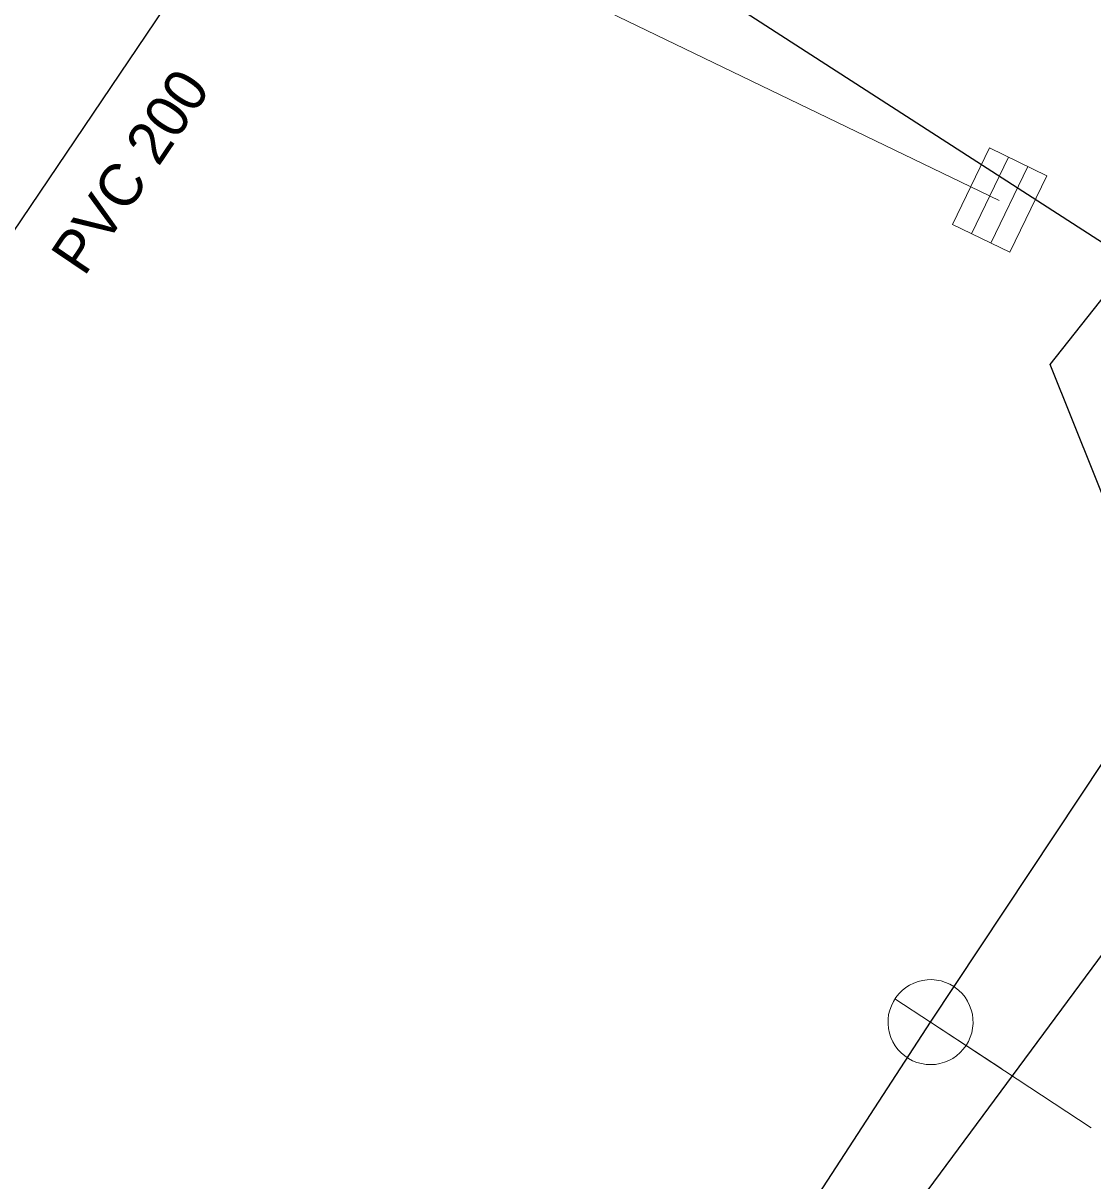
# Model space of a CAD drawing. Extents: x -791337 to -790755, y -988454 to -987923.
# Drawn here: x -791070.03 to -791044.88, y -988066.45 to -988039.22 of the extents above; entities that cross this region are included whole.
import ezdxf

# ---------------------------------------------------------------- set-up
doc = ezdxf.new("R2010")
doc.units = 0
doc.header["$LTSCALE"] = 0.4
for name, color, linetype, lineweight in [('1', 7, 'Continuous', 13), ('11', 7, 'Continuous', 13), ('14', 7, 'Continuous', 25), ('17', 7, 'Continuous', 25), ('22', 7, 'Continuous', 13)]:
    doc.layers.add(name, color=color, linetype=linetype, lineweight=lineweight)

msp = doc.modelspace()

# ---------------------------------------------------------------- linework, layer by layer
at = {"layer": '11'}
for p, q in [((-791047.079, -988043.389), (-791064.19, -988035.129)), ((-791044.912, -988065.203), (-791048.694, -988062.718))]:
    msp.add_line(p, q, dxfattribs=at)
at = {"layer": '14'}
msp.add_line((-791064.119, -988086.467), (-791048.694, -988062.718), dxfattribs=at)
for points in [[(-791080.519, -988059.839), (-791072.379, -988047.249), (-791064.19, -988035.129)], [(-791048.694, -988062.718), (-791034.09, -988040.71), (-791000.039, -988062.309)]]:
    msp.add_lwpolyline(points, dxfattribs=at)
at = {"layer": '17'}
for points in [[(-791043.809, -988044.929), (-791080.872, -988021.03), (-791082.371, -988020.047)], [(-791060.415, -988083.824), (-791052.313, -988071.484), (-791043.758, -988059.914), (-791042.206, -988056.414), (-791045.877, -988047.25), (-791044.421, -988045.406)]]:
    msp.add_lwpolyline(points, dxfattribs=at)
at = {"layer": '22'}
for p, q in [((-791046.858, -988042.372), (-791047.728, -988044.173)), ((-791046.408, -988042.59), (-791047.277, -988044.391)), ((-791047.02, -988063.813), (-791049.53, -988062.17))]:
    msp.add_line(p, q, dxfattribs=at)
for points in [[(-791045.958, -988042.807), (-791046.827, -988044.608), (-791048.178, -988043.956), (-791047.309, -988042.155)], [(-791048.145, -988061.881), (-791048.24, -988061.826), (-791048.34, -988061.782), (-791048.445, -988061.749), (-791048.551, -988061.728), (-791048.661, -988061.718), (-791048.77, -988061.72), (-791048.879, -988061.735), (-791048.985, -988061.762), (-791049.088, -988061.799), (-791049.186, -988061.848), (-791049.278, -988061.907), (-791049.363, -988061.976), (-791049.441, -988062.054), (-791049.509, -988062.14), (-791049.567, -988062.233), (-791049.615, -988062.331), (-791049.652, -988062.434), (-791049.678, -988062.54), (-791049.69, -988062.649), (-791049.692, -988062.758), (-791049.682, -988062.868), (-791049.66, -988062.974), (-791049.625, -988063.079), (-791049.581, -988063.179), (-791049.525, -988063.273), (-791049.459, -988063.36), (-791049.384, -988063.44), (-791049.301, -988063.511), (-791049.21, -988063.573), (-791049.114, -988063.625), (-791049.013, -988063.666), (-791048.907, -988063.694), (-791048.799, -988063.712), (-791048.69, -988063.718), (-791048.58, -988063.711), (-791048.472, -988063.693), (-791048.367, -988063.663), (-791048.265, -988063.622), (-791048.169, -988063.57), (-791048.079, -988063.507), (-791047.997, -988063.436), (-791047.922, -988063.355), (-791047.857, -988063.266), (-791047.802, -988063.172), (-791047.758, -988063.072), (-791047.725, -988062.968), (-791047.703, -988062.86), (-791047.694, -988062.751), (-791047.696, -988062.641), (-791047.71, -988062.533), (-791047.736, -988062.426), (-791047.774, -988062.324), (-791047.822, -988062.225), (-791047.882, -988062.134), (-791047.95, -988062.048), (-791048.028, -988061.971), (-791048.114, -988061.903)]]:
    msp.add_lwpolyline(points, close=True, dxfattribs=at)

# ---------------------------------------------------------------- texts
at = {"layer": '1'}
msp.add_text('PVC 200 ', height=1, rotation=56, dxfattribs=at).set_placement((-791068.599, -988045.2))

doc.saveas('drawing.dxf')
